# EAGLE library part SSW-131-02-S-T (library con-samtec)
THROUGH-HOLE .025" SQ POST SOCKET Source: Samtec SSW.pdf
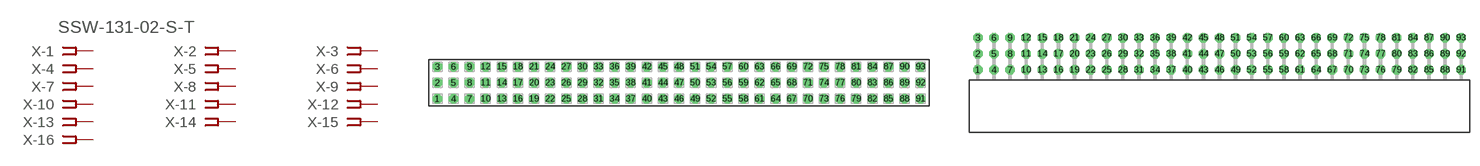
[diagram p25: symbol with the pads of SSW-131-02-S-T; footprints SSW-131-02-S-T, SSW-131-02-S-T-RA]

Designator prefix X; gates -1=FPINV -2=FPIN -3=FPIN -4=FPIN -5=FPIN -6=FPIN -7=FPIN -8=FPIN -9=FPIN -10=FPIN -11=FPIN -12=FPIN -13=FPIN -14=FPIN -15=FPIN -16=FPIN -17=FPIN -18=FPIN -19=FPIN -20=FPIN -21=FPIN -22=FPIN -23=FPIN -24=FPIN -25=FPIN -26=FPIN -27=FPIN -28=FPIN -29=FPIN -30=FPIN -31=FPIN -32=FPIN -33=FPIN -34=FPIN -35=FPIN -36=FPIN -37=FPIN -38=FPIN -39=FPIN -40=FPIN -41=FPIN -42=FPIN -43=FPIN -44=FPIN -45=FPIN -46=FPIN -47=FPIN -48=FPIN -49=FPIN -50=FPIN -51=FPIN -52=FPIN -53=FPIN -54=FPIN -55=FPIN -56=FPIN -57=FPIN -58=FPIN -59=FPIN -60=FPIN -61=FPIN -62=FPIN -63=FPIN -64=FPIN -65=FPIN -66=FPIN -67=FPIN -68=FPIN -69=FPIN -70=FPIN -71=FPIN -72=FPIN -73=FPIN -74=FPIN -75=FPIN -76=FPIN -77=FPIN -78=FPIN -79=FPIN -80=FPIN -81=FPIN -82=FPIN -83=FPIN -84=FPIN -85=FPIN -86=FPIN -87=FPIN -88=FPIN -89=FPIN -90=FPIN -91=FPIN -92=FPIN -93=FPIN

## SSW-131-02-S-T (OC_FARNELL: unknown; OC_NEWARK: unknown)  [SSW-131-02-S-T]
1  -1:1  pas
2  -2:1  pas
3  -3:1  pas
4  -4:1  pas
5  -5:1  pas
6  -6:1  pas
7  -7:1  pas
8  -8:1  pas
9  -9:1  pas
10  -10:1  pas
11  -11:1  pas
12  -12:1  pas
13  -13:1  pas
14  -14:1  pas
15  -15:1  pas
16  -16:1  pas
17  -17:1  pas
18  -18:1  pas
19  -19:1  pas
20  -20:1  pas
21  -21:1  pas
22  -22:1  pas
23  -23:1  pas
24  -24:1  pas
25  -25:1  pas
26  -26:1  pas
27  -27:1  pas
28  -28:1  pas
29  -29:1  pas
30  -30:1  pas
31  -31:1  pas
32  -32:1  pas
33  -33:1  pas
34  -34:1  pas
35  -35:1  pas
36  -36:1  pas
37  -37:1  pas
38  -38:1  pas
39  -39:1  pas
40  -40:1  pas
41  -41:1  pas
42  -42:1  pas
43  -43:1  pas
44  -44:1  pas
45  -45:1  pas
46  -46:1  pas
47  -47:1  pas
48  -48:1  pas
49  -49:1  pas
50  -50:1  pas
51  -51:1  pas
52  -52:1  pas
53  -53:1  pas
54  -54:1  pas
55  -55:1  pas
56  -56:1  pas
57  -57:1  pas
58  -58:1  pas
59  -59:1  pas
60  -60:1  pas
61  -61:1  pas
62  -62:1  pas
63  -63:1  pas
64  -64:1  pas
65  -65:1  pas
66  -66:1  pas
67  -67:1  pas
68  -68:1  pas
69  -69:1  pas
70  -70:1  pas
71  -71:1  pas
72  -72:1  pas
73  -73:1  pas
74  -74:1  pas
75  -75:1  pas
76  -76:1  pas
77  -77:1  pas
78  -78:1  pas
79  -79:1  pas
80  -80:1  pas
81  -81:1  pas
82  -82:1  pas
83  -83:1  pas
84  -84:1  pas
85  -85:1  pas
86  -86:1  pas
87  -87:1  pas
88  -88:1  pas
89  -89:1  pas
90  -90:1  pas
91  -91:1  pas
92  -92:1  pas
93  -93:1  pas

## SSW-131-02-S-TRA (OC_FARNELL: unknown; OC_NEWARK: unknown)  [SSW-131-02-S-T-RA]
Pads as for SSW-131-02-S-T

## Footprint SSW-131-02-S-T (pad centres in mm)
THROUGH-HOLE .025" SQ POST SOCKET Source: Samtec SSW.pdf
drill 1 pad 1.5 octagon: 1 -38.1,-2.54; 2 -38.1,0; 3 -38.1,2.54; 4 -35.56,-2.54; 5 -35.56,0; 6 -35.56,2.54; 7 -33.02,-2.54; 8 -33.02,0; 9 -33.02,2.54; 10 -30.48,-2.54; 11 -30.48,0; 12 -30.48,2.54; 13 -27.94,-2.54; 14 -27.94,0; 15 -27.94,2.54; 16 -25.4,-2.54; 17 -25.4,0; 18 -25.4,2.54; 19 -22.86,-2.54; 20 -22.86,0; 21 -22.86,2.54; 22 -20.32,-2.54; 23 -20.32,0; 24 -20.32,2.54; 25 -17.78,-2.54; 26 -17.78,0; 27 -17.78,2.54; 28 -15.24,-2.54; 29 -15.24,0; 30 -15.24,2.54; 31 -12.7,-2.54; 32 -12.7,0; 33 -12.7,2.54; 34 -10.16,-2.54; 35 -10.16,0; 36 -10.16,2.54; 37 -7.62,-2.54; 38 -7.62,0; 39 -7.62,2.54; 40 -5.08,-2.54; 41 -5.08,0; 42 -5.08,2.54; 43 -2.54,-2.54; 44 -2.54,0; 45 -2.54,2.54; 46 0,-2.54; 47 0,0; 48 0,2.54; 49 2.54,-2.54; 50 2.54,0; 51 2.54,2.54; 52 5.08,-2.54; 53 5.08,0; 54 5.08,2.54; 55 7.62,-2.54; 56 7.62,0; 57 7.62,2.54; 58 10.16,-2.54; 59 10.16,0; 60 10.16,2.54; 61 12.7,-2.54; 62 12.7,0; 63 12.7,2.54; 64 15.24,-2.54; 65 15.24,0; 66 15.24,2.54; 67 17.78,-2.54; 68 17.78,0; 69 17.78,2.54; 70 20.32,-2.54; 71 20.32,0; 72 20.32,2.54; 73 22.86,-2.54; 74 22.86,0; 75 22.86,2.54; 76 25.4,-2.54; 77 25.4,0; 78 25.4,2.54; 79 27.94,-2.54; 80 27.94,0; 81 27.94,2.54; 82 30.48,-2.54; 83 30.48,0; 84 30.48,2.54; 85 33.02,-2.54; 86 33.02,0; 87 33.02,2.54; 88 35.56,-2.54; 89 35.56,0; 90 35.56,2.54; 91 38.1,-2.54; 92 38.1,0; 93 38.1,2.54

## Footprint SSW-131-02-S-T-RA (pad centres in mm)
THROUGH-HOLE .025" SQ POST SOCKET Source: Samtec SSW.pdf
drill 1 pad 1.5 octagon: 1 -38.1,1.524; 2 -38.1,4.064; 3 -38.1,6.604; 4 -35.56,1.524; 5 -35.56,4.064; 6 -35.56,6.604; 7 -33.02,1.524; 8 -33.02,4.064; 9 -33.02,6.604; 10 -30.48,1.524; 11 -30.48,4.064; 12 -30.48,6.604; 13 -27.94,1.524; 14 -27.94,4.064; 15 -27.94,6.604; 16 -25.4,1.524; 17 -25.4,4.064; 18 -25.4,6.604; 19 -22.86,1.524; 20 -22.86,4.064; 21 -22.86,6.604; 22 -20.32,1.524; 23 -20.32,4.064; 24 -20.32,6.604; 25 -17.78,1.524; 26 -17.78,4.064; 27 -17.78,6.604; 28 -15.24,1.524; 29 -15.24,4.064; 30 -15.24,6.604; 31 -12.7,1.524; 32 -12.7,4.064; 33 -12.7,6.604; 34 -10.16,1.524; 35 -10.16,4.064; 36 -10.16,6.604; 37 -7.62,1.524; 38 -7.62,4.064; 39 -7.62,6.604; 40 -5.08,1.524; 41 -5.08,4.064; 42 -5.08,6.604; 43 -2.54,1.524; 44 -2.54,4.064; 45 -2.54,6.604; 46 0,1.524; 47 0,4.064; 48 0,6.604; 49 2.54,1.524; 50 2.54,4.064; 51 2.54,6.604; 52 5.08,1.524; 53 5.08,4.064; 54 5.08,6.604; 55 7.62,1.524; 56 7.62,4.064; 57 7.62,6.604; 58 10.16,1.524; 59 10.16,4.064; 60 10.16,6.604; 61 12.7,1.524; 62 12.7,4.064; 63 12.7,6.604; 64 15.24,1.524; 65 15.24,4.064; 66 15.24,6.604; 67 17.78,1.524; 68 17.78,4.064; 69 17.78,6.604; 70 20.32,1.524; 71 20.32,4.064; 72 20.32,6.604; 73 22.86,1.524; 74 22.86,4.064; 75 22.86,6.604; 76 25.4,1.524; 77 25.4,4.064; 78 25.4,6.604; 79 27.94,1.524; 80 27.94,4.064; 81 27.94,6.604; 82 30.48,1.524; 83 30.48,4.064; 84 30.48,6.604; 85 33.02,1.524; 86 33.02,4.064; 87 33.02,6.604; 88 35.56,1.524; 89 35.56,4.064; 90 35.56,6.604; 91 38.1,1.524; 92 38.1,4.064; 93 38.1,6.604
